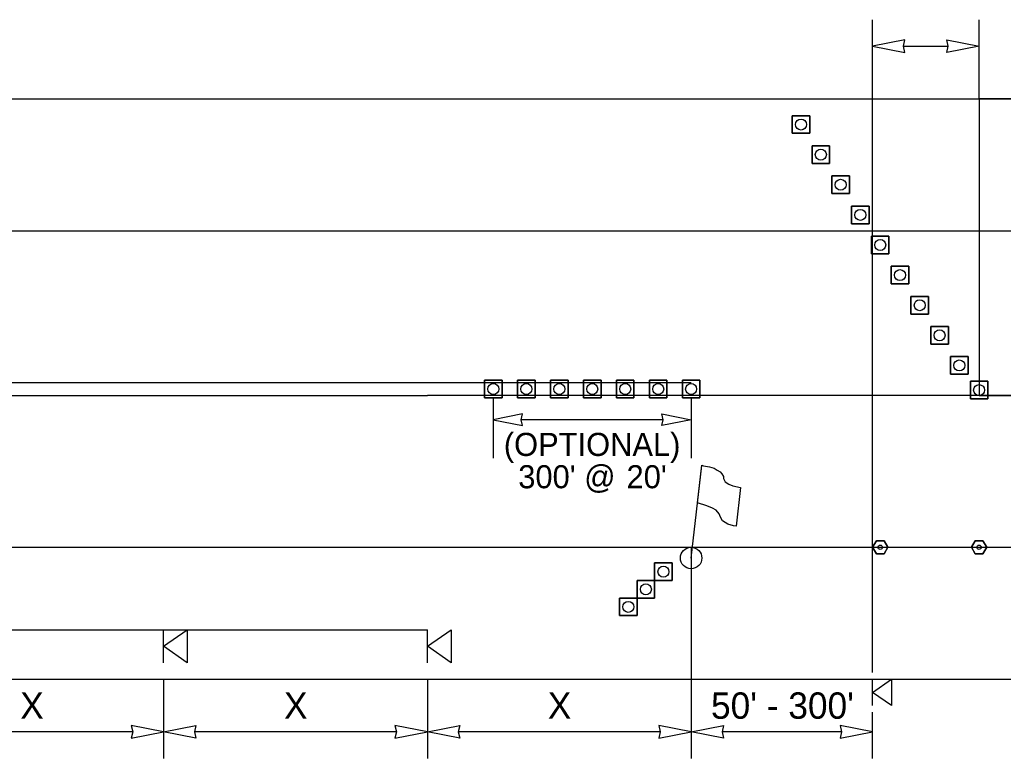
# Model space of a CAD drawing. Extents: x 99999.1 to 100095.7, y 99995 to 100010.7.
# Drawn here: x 100042.24 to 100045.223, y 100005.492 to 100007.732 of the extents above; entities that cross this region are included whole.
import ezdxf

# ---------------------------------------------------------------- set-up
doc = ezdxf.new("R2010")
doc.units = 0
for name, color, linetype in [('RD_ED_ShoulderPavedEdge', 7, 'Continuous'), ('RD_MK_LineDblYellowCenter', 7, 'Continuous'), ('RD_MK_LineEdgeWhite', 7, 'Continuous'), ('RD_MK_LineNoPass', 7, 'Continuous'), ('RD_MK_LineSkipCenter', 7, 'Continuous'), ('TR_WZ_FlaggingStation', 7, 'Continuous'), ('TR_WZ_PortableSignMountBlk-Org', 7, 'Continuous'), ('TR_WZ_PortableSignMountBlk-Wht', 7, 'Continuous'), ('TR_WZ_TrafficCone', 7, 'Continuous'), ('TR_WZ_TubularMarker', 7, 'Continuous'), ('TR_WZ_WorkZoneDetails', 7, 'Continuous'), ('TR_WZ_WorkZoneTextCurrent', 7, 'Continuous')]:
    doc.layers.add(name, color=color, linetype=linetype)

msp = doc.modelspace()

# ---------------------------------------------------------------- linework, layer by layer
at = {"layer": 'RD_ED_ShoulderPavedEdge'}
for p, q in [((100040.1076, 100007.4923), (100055.6424, 100007.4923)), ((100040.1076, 100005.7323), (100055.6424, 100005.7323))]:
    msp.add_line(p, q, dxfattribs=at)
at = {"layer": 'RD_MK_LineDblYellowCenter'}
for p, q in [((100040.1282, 100006.6323), (100043.4767, 100006.6323)), ((100040.0869, 100006.5923), (100043.4767, 100006.5923))]:
    msp.add_line(p, q, dxfattribs=at)
at = {"layer": 'RD_MK_LineEdgeWhite'}
for p, q in [((100040.1076, 100007.0923), (100055.6424, 100007.0923)), ((100040.1076, 100006.1323), (100055.6424, 100006.1323))]:
    msp.add_line(p, q, dxfattribs=at)
at = {"layer": 'RD_MK_LineNoPass'}
msp.add_line((100043.4767, 100006.6323), (100044.2767, 100006.6323), dxfattribs=at)
at = {"layer": 'RD_MK_LineSkipCenter'}
msp.add_lwpolyline([(100051.15, 100006.5923), (100043.4767, 100006.5923)], dxfattribs=at)
at = {"layer": 'TR_WZ_FlaggingStation'}
for p, q in [((100044.2767, 100006.0998), (100044.3087, 100006.3808)), ((100044.2957, 100006.2667), (100044.3087, 100006.3811)), ((100044.4267, 100006.3133), (100044.4134, 100006.1961)), ((100044.2957, 100006.2667), (100044.2957, 100006.2667))]:
    msp.add_line(p, q, dxfattribs=at)
for points in [[(100044.3087, 100006.3811), (100044.3145, 100006.3798), (100044.3323, 100006.3764), (100044.3461, 100006.3722), (100044.3558, 100006.3661), (100044.3643, 100006.3614), (100044.37, 100006.3546), (100044.3743, 100006.3467), (100044.3748, 100006.3405), (100044.3802, 100006.3313), (100044.391, 100006.3239), (100044.4034, 100006.3187), (100044.4267, 100006.3133)], [(100044.4134, 100006.1961), (100044.4052, 100006.1975), (100044.3876, 100006.2021), (100044.3719, 100006.2126), (100044.3654, 100006.2232), (100044.3615, 100006.2335), (100044.3524, 100006.2444), (100044.3414, 100006.2506), (100044.3241, 100006.2577), (100044.2957, 100006.2667)]]:
    msp.add_lwpolyline(points, dxfattribs=at)
msp.add_circle((100044.2767, 100006.0998), 0.0325, dxfattribs=at)
at = {"layer": 'TR_WZ_PortableSignMountBlk-Org'}
for p, q in [((100042.6767, 100005.7824), (100042.6767, 100005.8824)), ((100043.4767, 100005.7824), (100043.4767, 100005.8824))]:
    msp.add_line(p, q, dxfattribs=at)
for points in [[(100042.6767, 100005.8323), (100042.7485, 100005.8824), (100042.7485, 100005.7824)], [(100043.4767, 100005.8323), (100043.5485, 100005.8824), (100043.5485, 100005.7824)]]:
    msp.add_lwpolyline(points, close=True, dxfattribs=at)
at = {"layer": 'TR_WZ_PortableSignMountBlk-Wht'}
msp.add_line((100044.8267, 100005.6523), (100044.8267, 100005.7323), dxfattribs=at)
msp.add_lwpolyline([(100044.8267, 100005.6923), (100044.8841, 100005.7323), (100044.8841, 100005.6523)], close=True, dxfattribs=at)
at = {"layer": 'TR_WZ_TrafficCone'}
for points in [[(100044.6367, 100007.4411), (100044.5834, 100007.4411), (100044.5834, 100007.3877), (100044.6367, 100007.3877), (100044.6367, 100007.4411)], [(100044.6367, 100007.3877), (100044.5834, 100007.3877), (100044.5834, 100007.4411), (100044.6367, 100007.4411), (100044.6367, 100007.3877)], [(100044.6967, 100007.3497), (100044.6434, 100007.3497), (100044.6434, 100007.2964), (100044.6967, 100007.2964), (100044.6967, 100007.3497)], [(100044.6967, 100007.2964), (100044.6434, 100007.2964), (100044.6434, 100007.3497), (100044.6967, 100007.3497), (100044.6967, 100007.2964)], [(100044.7567, 100007.2584), (100044.7034, 100007.2584), (100044.7034, 100007.2051), (100044.7567, 100007.2051), (100044.7567, 100007.2584)], [(100044.7567, 100007.2051), (100044.7034, 100007.2051), (100044.7034, 100007.2584), (100044.7567, 100007.2584), (100044.7567, 100007.2051)], [(100044.8167, 100007.1671), (100044.7634, 100007.1671), (100044.7634, 100007.1137), (100044.8167, 100007.1137), (100044.8167, 100007.1671)], [(100044.8167, 100007.1137), (100044.7634, 100007.1137), (100044.7634, 100007.1671), (100044.8167, 100007.1671), (100044.8167, 100007.1137)], [(100044.8234, 100007.0757), (100044.8767, 100007.0757), (100044.8767, 100007.0224), (100044.8234, 100007.0224), (100044.8234, 100007.0757)], [(100044.8234, 100007.0224), (100044.8767, 100007.0224), (100044.8767, 100007.0757), (100044.8234, 100007.0757), (100044.8234, 100007.0224)], [(100044.8834, 100006.9844), (100044.9367, 100006.9844), (100044.9367, 100006.9311), (100044.8834, 100006.9311), (100044.8834, 100006.9844)], [(100044.8834, 100006.9311), (100044.9367, 100006.9311), (100044.9367, 100006.9844), (100044.8834, 100006.9844), (100044.8834, 100006.9311)], [(100044.9434, 100006.8931), (100044.9967, 100006.8931), (100044.9967, 100006.8397), (100044.9434, 100006.8397), (100044.9434, 100006.8931)], [(100044.9434, 100006.8397), (100044.9967, 100006.8397), (100044.9967, 100006.8931), (100044.9434, 100006.8931), (100044.9434, 100006.8397)], [(100045.0034, 100006.8017), (100045.0567, 100006.8017), (100045.0567, 100006.7484), (100045.0034, 100006.7484), (100045.0034, 100006.8017)], [(100045.0034, 100006.7484), (100045.0567, 100006.7484), (100045.0567, 100006.8017), (100045.0034, 100006.8017), (100045.0034, 100006.7484)], [(100045.0634, 100006.7104), (100045.1167, 100006.7104), (100045.1167, 100006.6571), (100045.0634, 100006.6571), (100045.0634, 100006.7104)], [(100045.0634, 100006.6571), (100045.1167, 100006.6571), (100045.1167, 100006.7104), (100045.0634, 100006.7104), (100045.0634, 100006.6571)], [(100043.7033, 100006.639), (100043.65, 100006.639), (100043.65, 100006.5857), (100043.7033, 100006.5857), (100043.7033, 100006.639)], [(100043.7033, 100006.5857), (100043.65, 100006.5857), (100043.65, 100006.639), (100043.7033, 100006.639), (100043.7033, 100006.5857)], [(100043.8033, 100006.639), (100043.75, 100006.639), (100043.75, 100006.5857), (100043.8033, 100006.5857), (100043.8033, 100006.639)], [(100043.8033, 100006.5857), (100043.75, 100006.5857), (100043.75, 100006.639), (100043.8033, 100006.639), (100043.8033, 100006.5857)], [(100043.9033, 100006.639), (100043.85, 100006.639), (100043.85, 100006.5857), (100043.9033, 100006.5857), (100043.9033, 100006.639)], [(100043.9033, 100006.5857), (100043.85, 100006.5857), (100043.85, 100006.639), (100043.9033, 100006.639), (100043.9033, 100006.5857)], [(100044.0033, 100006.639), (100043.95, 100006.639), (100043.95, 100006.5857), (100044.0033, 100006.5857), (100044.0033, 100006.639)], [(100044.0033, 100006.5857), (100043.95, 100006.5857), (100043.95, 100006.639), (100044.0033, 100006.639), (100044.0033, 100006.5857)], [(100044.1033, 100006.639), (100044.05, 100006.639), (100044.05, 100006.5857), (100044.1033, 100006.5857), (100044.1033, 100006.639)], [(100044.1033, 100006.5857), (100044.05, 100006.5857), (100044.05, 100006.639), (100044.1033, 100006.639), (100044.1033, 100006.5857)], [(100044.2033, 100006.639), (100044.15, 100006.639), (100044.15, 100006.5857), (100044.2033, 100006.5857), (100044.2033, 100006.639)], [(100044.2033, 100006.5857), (100044.15, 100006.5857), (100044.15, 100006.639), (100044.2033, 100006.639), (100044.2033, 100006.5857)], [(100044.3033, 100006.639), (100044.25, 100006.639), (100044.25, 100006.5857), (100044.3033, 100006.5857), (100044.3033, 100006.639)], [(100044.3033, 100006.5857), (100044.25, 100006.5857), (100044.25, 100006.639), (100044.3033, 100006.639), (100044.3033, 100006.5857)], [(100045.1234, 100006.6357), (100045.1767, 100006.6357), (100045.1767, 100006.5823), (100045.1234, 100006.5823), (100045.1234, 100006.6357)], [(100045.1234, 100006.5823), (100045.1767, 100006.5823), (100045.1767, 100006.6357), (100045.1234, 100006.6357), (100045.1234, 100006.5823)], [(100044.166, 100006.085), (100044.2193, 100006.085), (100044.2193, 100006.0317), (100044.166, 100006.0317), (100044.166, 100006.085)], [(100044.166, 100006.0317), (100044.2193, 100006.0317), (100044.2193, 100006.085), (100044.166, 100006.085), (100044.166, 100006.0317)], [(100044.1127, 100006.0317), (100044.166, 100006.0317), (100044.166, 100005.9783), (100044.1127, 100005.9783), (100044.1127, 100006.0317)], [(100044.1127, 100005.9783), (100044.166, 100005.9783), (100044.166, 100006.0317), (100044.1127, 100006.0317), (100044.1127, 100005.9783)], [(100044.0593, 100005.9783), (100044.1127, 100005.9783), (100044.1127, 100005.925), (100044.0593, 100005.925), (100044.0593, 100005.9783)], [(100044.0593, 100005.925), (100044.1127, 100005.925), (100044.1127, 100005.9783), (100044.0593, 100005.9783), (100044.0593, 100005.925)]]:
    msp.add_lwpolyline(points, dxfattribs=at)
for centre in [(100044.61, 100007.4144), (100044.67, 100007.3231), (100044.73, 100007.2317), (100044.79, 100007.1404), (100044.85, 100007.0491), (100044.91, 100006.9577), (100044.97, 100006.8664), (100045.03, 100006.7751), (100045.09, 100006.6837), (100043.6767, 100006.6123), (100043.7767, 100006.6123), (100043.8767, 100006.6123), (100043.9767, 100006.6123), (100044.0767, 100006.6123), (100044.1767, 100006.6123), (100044.2767, 100006.6123), (100045.15, 100006.609), (100044.1927, 100006.0583), (100044.1393, 100006.005), (100044.086, 100005.9517)]:
    msp.add_circle(centre, 0.0167, dxfattribs=at)
at = {"layer": 'TR_WZ_TubularMarker'}
for points in [[(100044.8269, 100006.1323), (100044.8385, 100006.1523), (100044.8616, 100006.1523), (100044.8731, 100006.1323), (100044.8616, 100006.1123), (100044.8385, 100006.1123)], [(100045.1269, 100006.1323), (100045.1385, 100006.1523), (100045.1616, 100006.1523), (100045.1731, 100006.1323), (100045.1616, 100006.1123), (100045.1385, 100006.1123)]]:
    msp.add_lwpolyline(points, close=True, dxfattribs=at)
for points in [[(100044.8385, 100006.1123), (100044.8616, 100006.1123), (100044.8731, 100006.1323), (100044.8616, 100006.1523), (100044.8385, 100006.1523), (100044.8269, 100006.1323), (100044.8385, 100006.1123)], [(100045.1385, 100006.1123), (100045.1616, 100006.1123), (100045.1731, 100006.1323), (100045.1616, 100006.1523), (100045.1385, 100006.1523), (100045.1269, 100006.1323), (100045.1385, 100006.1123)]]:
    msp.add_lwpolyline(points, dxfattribs=at)
for centre in [(100044.85, 100006.1323), (100045.15, 100006.1323)]:
    msp.add_circle(centre, 0.00667, dxfattribs=at)
at = {"layer": 'TR_WZ_WorkZoneDetails'}
for p, q in [((100044.8267, 100005.7523), (100044.8267, 100007.7323)), ((100045.15, 100007.4923), (100045.15, 100007.7323)), ((100044.9204, 100007.6523), (100045.0563, 100007.6523)), ((100043.6767, 100006.5857), (100043.6767, 100006.4023)), ((100044.2767, 100006.5857), (100044.2767, 100006.4023)), ((100044.1923, 100006.5193), (100043.761, 100006.5193)), ((100044.2767, 100006.1323), (100044.2767, 100005.4923)), ((100041.0767, 100005.8824), (100043.4767, 100005.8824)), ((100042.6767, 100005.7323), (100042.6767, 100005.4923)), ((100043.4767, 100005.7323), (100043.4767, 100005.4923)), ((100044.8267, 100005.4923), (100044.8267, 100005.6319)), ((100042.5829, 100005.5723), (100041.9704, 100005.5723)), ((100043.3829, 100005.5723), (100042.7704, 100005.5723)), ((100044.1829, 100005.5723), (100043.5704, 100005.5723)), ((100044.7329, 100005.5723), (100044.3704, 100005.5723))]:
    msp.add_line(p, q, dxfattribs=at)
for points in [[(100044.8267, 100007.6523), (100044.9249, 100007.6331), (100044.9204, 100007.6523), (100044.9249, 100007.6716)], [(100045.15, 100007.6523), (100045.0517, 100007.6331), (100045.0563, 100007.6523), (100045.0517, 100007.6716)], [(100045.15, 100007.4923), (100045.15, 100006.5923), (100049.9338, 100006.5923), (100049.9338, 100007.4923)], [(100043.6767, 100006.5193), (100043.7651, 100006.502), (100043.761, 100006.5193), (100043.7651, 100006.5367)], [(100044.2767, 100006.5193), (100044.1882, 100006.502), (100044.1923, 100006.5193), (100044.1882, 100006.5367)], [(100042.6767, 100005.5723), (100042.5784, 100005.5916), (100042.5829, 100005.5723), (100042.5784, 100005.5531)], [(100042.6767, 100005.5723), (100042.7749, 100005.5916), (100042.7704, 100005.5723), (100042.7749, 100005.5531)], [(100043.4767, 100005.5723), (100043.3784, 100005.5916), (100043.3829, 100005.5723), (100043.3784, 100005.5531)], [(100043.4767, 100005.5723), (100043.5749, 100005.5916), (100043.5704, 100005.5723), (100043.5749, 100005.5531)], [(100044.2767, 100005.5723), (100044.1784, 100005.5916), (100044.1829, 100005.5723), (100044.1784, 100005.5531)], [(100044.2767, 100005.5723), (100044.3749, 100005.5916), (100044.3704, 100005.5723), (100044.3749, 100005.5531)], [(100044.8267, 100005.5723), (100044.7284, 100005.5916), (100044.7329, 100005.5723), (100044.7284, 100005.5531)]]:
    msp.add_lwpolyline(points, close=True, dxfattribs=at)

# ---------------------------------------------------------------- texts
at = {"layer": 'TR_WZ_WorkZoneTextCurrent'}
for s, p in [('(OPTIONAL)', (100043.7085, 100006.4093)), ("300' @", (100043.7523, 100006.3113)), ("20'", (100044.0807, 100006.3113))]:
    msp.add_text(s, height=0.07, dxfattribs=at).set_placement(p)
for s, p in [('X', (100042.2419, 100005.6123)), ('X', (100043.0419, 100005.6123)), ('X', (100043.8419, 100005.6123)), ("50' - 300'", (100044.3369, 100005.6123))]:
    msp.add_text(s, height=0.08, rotation=360, dxfattribs=at).set_placement(p)

doc.saveas('drawing.dxf')
